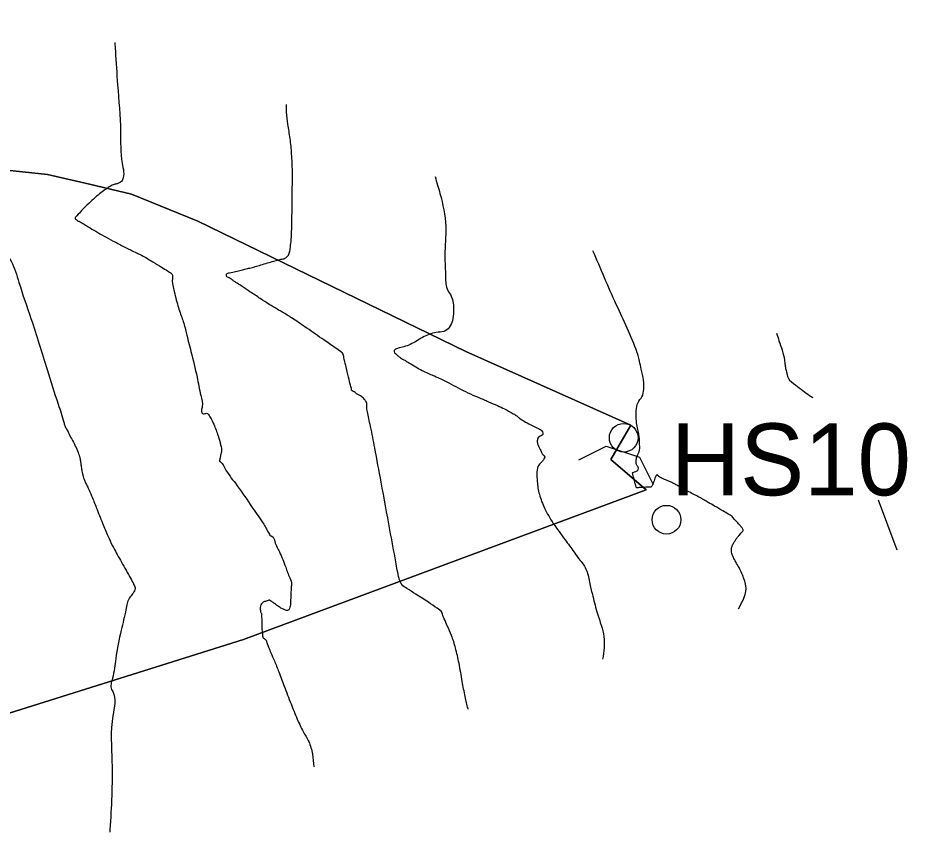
# Model space of a CAD drawing. Extents: x -478495 to -472450, y -1118050 to -1113745.
# Drawn here: x -476892.7 to -476768.9, y -1116354.3 to -1116241 of the extents above; entities that cross this region are included whole.
import ezdxf

# ---------------------------------------------------------------- set-up
doc = ezdxf.new("R2010")
doc.units = 0
for name, color, linetype in [('cesty', 7, 'Continuous'), ('hospodářské sjezdy', 7, 'Continuous'), ('ObPÚ', 7, 'Continuous'), ('Vrstevnice_hlavni', 7, 'Continuous'), ('Vrstevnice_vedlejsi', 7, 'Continuous')]:
    doc.layers.add(name, color=color, linetype=linetype)

msp = doc.modelspace()

# ---------------------------------------------------------------- linework, layer by layer
at = {"layer": 'cesty'}
for centre in [(-476808.34, -1116299.4), (-476802.39, -1116310.81)]:
    msp.add_circle(centre, 2, dxfattribs=at)
at = {"layer": 'hospodářské sjezdy'}
for p, q in [((-476814.6, -1116302.47), (-476810.79, -1116300.56)), ((-476810.79, -1116300.56), (-476806.15, -1116302.09)), ((-476806.15, -1116302.09), (-476804.23, -1116305.9))]:
    msp.add_line(p, q, dxfattribs=at)
at = {"layer": 'ObPÚ'}
for p, q in [((-476908.04, -1116260.74), (-476888.56, -1116262.76)), ((-476888.56, -1116262.76), (-476908.04, -1116260.74)), ((-476888.56, -1116262.76), (-476882.72, -1116264.13)), ((-476882.72, -1116264.13), (-476888.56, -1116262.76)), ((-476882.72, -1116264.13), (-476876.87, -1116265.5)), ((-476876.87, -1116265.5), (-476882.72, -1116264.13)), ((-476876.87, -1116265.5), (-476867.65, -1116269.24)), ((-476867.65, -1116269.24), (-476876.87, -1116265.5)), ((-476867.65, -1116269.24), (-476830.31, -1116287.39)), ((-476830.31, -1116287.39), (-476867.65, -1116269.24)), ((-476830.31, -1116287.39), (-476807.36, -1116297.66)), ((-476807.36, -1116297.66), (-476830.31, -1116287.39)), ((-476807.36, -1116297.66), (-476810.13, -1116302.43)), ((-476810.13, -1116302.43), (-476807.36, -1116297.66)), ((-476810.13, -1116302.43), (-476805.23, -1116306.64)), ((-476805.23, -1116306.64), (-476810.13, -1116302.43)), ((-476805.23, -1116306.64), (-476861.27, -1116327.48)), ((-476861.27, -1116327.48), (-476805.23, -1116306.64)), ((-476861.27, -1116327.48), (-476910.57, -1116342.96)), ((-476910.57, -1116342.96), (-476861.27, -1116327.48))]:
    msp.add_line(p, q, dxfattribs=at)
at = {"layer": 'Vrstevnice_hlavni'}
for points in [[(-476879.21, -1116244.41), (-476879.13, -1116245.59), (-476878.82, -1116250.29), (-476878.41, -1116256.78), (-476878.18, -1116261.19), (-476878.14, -1116263.5), (-476878.28, -1116263.72), (-476878.52, -1116263.9), (-476878.86, -1116264.05), (-476879.3, -1116264.16), (-476879.82, -1116264.41), (-476880.43, -1116264.79), (-476881.13, -1116265.3), (-476881.93, -1116265.97), (-476882.84, -1116266.8), (-476883.86, -1116267.79), (-476884.49, -1116268.5), (-476884.74, -1116268.91), (-476884.61, -1116269.04), (-476884.46, -1116269.14), (-476884.3, -1116269.24), (-476884.13, -1116269.31), (-476883.67, -1116269.57), (-476882.91, -1116270.03), (-476881.86, -1116270.67), (-476880.71, -1116271.33), (-476879.45, -1116272.02), (-476878.08, -1116272.72), (-476876.99, -1116273.27), (-476876.18, -1116273.67), (-476875.66, -1116273.91), (-476874.9, -1116274.33), (-476873.91, -1116274.91), (-476872.7, -1116275.65), (-476871.85, -1116276.18), (-476871.36, -1116276.5), (-476871.25, -1116276.6), (-476871.19, -1116276.79), (-476871.17, -1116277.1), (-476871.2, -1116277.5), (-476871.12, -1116278.15), (-476870.93, -1116279.06), (-476870.64, -1116280.23), (-476870.34, -1116281.28), (-476870.04, -1116282.22), (-476869.74, -1116283.03), (-476869.26, -1116284.77), (-476868.6, -1116287.41), (-476867.76, -1116290.96), (-476867.23, -1116293.51), (-476867.03, -1116295.06), (-476867.14, -1116295.59), (-476867.08, -1116295.93), (-476866.85, -1116296.07), (-476866.43, -1116296), (-476865.96, -1116296.49), (-476865.42, -1116297.53)], [(-476865.42, -1116297.53), (-476864.82, -1116299.12), (-476864.47, -1116300.4), (-476864.36, -1116301.35), (-476864.51, -1116301.99), (-476864.59, -1116302.43), (-476864.61, -1116302.67), (-476864.55, -1116302.72), (-476863.83, -1116303.73), (-476862.42, -1116305.73), (-476860.34, -1116308.69), (-476858.89, -1116310.81), (-476858.07, -1116312.09), (-476857.87, -1116312.53), (-476857.68, -1116312.84), (-476857.5, -1116313.03), (-476857.33, -1116313.1), (-476856.92, -1116313.85), (-476856.28, -1116315.28), (-476855.41, -1116317.4), (-476854.84, -1116318.91), (-476854.58, -1116319.81), (-476854.63, -1116320.11), (-476854.67, -1116320.66), (-476854.71, -1116321.45), (-476854.74, -1116322.5), (-476854.88, -1116323.16), (-476855.14, -1116323.45), (-476855.51, -1116323.36), (-476855.94, -1116323.16), (-476856.43, -1116322.87), (-476856.97, -1116322.48), (-476857.36, -1116322.21), (-476857.6, -1116322.05), (-476857.68, -1116322), (-476857.86, -1116322.03), (-476858.14, -1116322.13), (-476858.53, -1116322.3), (-476858.79, -1116322.53), (-476858.93, -1116322.83), (-476858.95, -1116323.18), (-476858.94, -1116323.45), (-476858.9, -1116323.64), (-476858.83, -1116323.76), (-476858.77, -1116324.2), (-476858.73, -1116324.97), (-476858.72, -1116326.07), (-476858.64, -1116326.84), (-476858.51, -1116327.29), (-476858.31, -1116327.42), (-476858.16, -1116327.58), (-476858.06, -1116327.78), (-476858, -1116328.02), (-476857.8, -1116328.54), (-476857.47, -1116329.35), (-476856.99, -1116330.44), (-476856.37, -1116331.98), (-476855.6, -1116333.98), (-476854.67, -1116336.44), (-476853.8, -1116338.55), (-476852.97, -1116340.3), (-476852.2, -1116341.69), (-476851.7, -1116343.42), (-476851.51, -1116345.19)]]:
    msp.add_spline(points, degree=3, dxfattribs=at)
at = {"layer": 'Vrstevnice_vedlejsi'}
msp.add_line((-476772.89, -1116308.03), (-476770.29, -1116314.98), dxfattribs=at)
for points in [[(-476904.91, -1116240.96), (-476904.89, -1116241.08), (-476904.25, -1116243.09), (-476904.01, -1116246.21), (-476904.18, -1116250.45), (-476904.76, -1116255.81), (-476905.12, -1116259.68), (-476905.25, -1116262.06), (-476905.17, -1116262.95), (-476905.07, -1116263.68), (-476904.96, -1116264.25), (-476904.83, -1116264.67), (-476904.55, -1116265.56), (-476904.1, -1116266.95), (-476903.5, -1116268.81), (-476902.73, -1116270.17), (-476901.79, -1116271.02), (-476900.68, -1116271.38), (-476899.6, -1116271.65), (-476898.56, -1116271.85), (-476897.54, -1116271.97), (-476896.76, -1116272.13), (-476896.22, -1116272.31), (-476895.92, -1116272.53), (-476895.67, -1116272.69), (-476895.49, -1116272.8), (-476895.36, -1116272.85), (-476895.21, -1116272.91), (-476895.04, -1116272.98), (-476894.85, -1116273.06), (-476894.56, -1116273.39), (-476894.16, -1116273.99), (-476893.65, -1116274.84), (-476892.56, -1116277.78), (-476890.88, -1116282.81), (-476888.63, -1116289.92), (-476887.1, -1116294.73), (-476886.3, -1116297.25), (-476886.24, -1116297.47), (-476886.15, -1116297.7), (-476886.05, -1116297.95), (-476885.92, -1116298.2), (-476885.66, -1116298.72), (-476885.25, -1116299.5), (-476884.71, -1116300.55), (-476884.31, -1116301.44), (-476884.07, -1116302.19), (-476883.97, -1116302.78), (-476883.9, -1116303.26), (-476883.85, -1116303.64), (-476883.81, -1116303.91), (-476883.75, -1116304.23), (-476883.66, -1116304.58), (-476883.55, -1116304.98), (-476883.38, -1116305.42), (-476883.17, -1116305.89), (-476882.91, -1116306.41), (-476882.44, -1116307.48), (-476881.78, -1116309.11), (-476880.92, -1116311.29), (-476880.17, -1116313.07), (-476879.53, -1116314.45)], [(-476862.17, -1116277.89), (-476862.52, -1116277.66), (-476862.88, -1116277.42), (-476863.26, -1116277.16), (-476863.66, -1116276.89), (-476863.64, -1116276.65), (-476863.22, -1116276.44), (-476862.38, -1116276.25), (-476861.61, -1116276.07), (-476860.9, -1116275.9), (-476860.24, -1116275.74), (-476859.49, -1116275.53), (-476858.65, -1116275.28), (-476857.72, -1116275), (-476856.9, -1116274.77), (-476856.21, -1116274.59), (-476855.64, -1116274.48), (-476855.21, -1116274.19), (-476854.92, -1116273.73), (-476854.78, -1116273.1), (-476854.67, -1116272.11), (-476854.59, -1116270.76), (-476854.55, -1116269.06), (-476854.51, -1116267.08), (-476854.49, -1116264.82), (-476854.48, -1116262.29), (-476854.58, -1116259.93), (-476854.79, -1116257.76), (-476855.11, -1116255.77), (-476855.29, -1116254.08), (-476855.32, -1116253)], [(-476834.61, -1116263.06), (-476833.93, -1116265.41), (-476833.13, -1116269.99), (-476833.24, -1116274.04), (-476833.15, -1116277), (-476832.85, -1116278.89), (-476832.36, -1116279.69), (-476832.09, -1116280.66), (-476832.03, -1116281.81), (-476832.19, -1116283.12), (-476832.64, -1116284.05), (-476833.4, -1116284.59), (-476834.45, -1116284.74), (-476835.43, -1116285.01), (-476836.35, -1116285.43), (-476837.2, -1116285.97), (-476838.06, -1116286.4), (-476838.95, -1116286.74), (-476839.85, -1116286.97), (-476840.29, -1116287.25), (-476840.26, -1116287.59)], [(-476804.28, -1116305.84), (-476804.37, -1116306.05), (-476804.48, -1116306.2), (-476804.58, -1116306.27), (-476804.69, -1116306.27), (-476804.92, -1116306.27), (-476805.26, -1116306.29), (-476805.72, -1116306.32), (-476806.08, -1116306.34), (-476806.32, -1116306.35), (-476806.45, -1116306.36), (-476806.55, -1116306.32), (-476806.62, -1116306.22), (-476806.66, -1116306.06), (-476806.73, -1116305.79), (-476806.83, -1116305.39), (-476806.97, -1116304.88), (-476807.06, -1116304.53), (-476807.12, -1116304.34), (-476807.15, -1116304.31), (-476807.05, -1116304.25), (-476806.82, -1116304.15), (-476806.47, -1116304.02), (-476806.31, -1116303.8), (-476806.34, -1116303.5), (-476806.56, -1116303.1), (-476806.62, -1116302.62), (-476806.5, -1116302.04), (-476806.21, -1116301.38), (-476806.12, -1116300.33), (-476806.24, -1116298.91), (-476806.57, -1116297.1), (-476806.6, -1116295.63), (-476806.35, -1116294.49), (-476805.8, -1116293.7), (-476805.54, -1116292.66), (-476805.57, -1116291.38), (-476805.89, -1116289.86), (-476806.14, -1116288.72), (-476806.33, -1116287.95), (-476806.46, -1116287.56), (-476809.37, -1116280.84), (-476812.62, -1116273.39)], [(-476830, -1116337.19), (-476830.02, -1116337.11), (-476830.41, -1116335.43), (-476830.83, -1116333.32), (-476831.27, -1116330.79), (-476831.77, -1116328.65), (-476832.32, -1116326.92), (-476832.91, -1116325.58), (-476833.33, -1116324.6), (-476833.59, -1116323.97), (-476833.67, -1116323.69), (-476834.32, -1116323.13), (-476835.53, -1116322.3), (-476837.31, -1116321.18), (-476838.55, -1116320.36), (-476839.24, -1116319.83), (-476839.38, -1116319.59), (-476839.49, -1116319.37), (-476839.58, -1116319.17), (-476839.63, -1116318.99), (-476840.08, -1116316.67), (-476840.9, -1116312.2), (-476842.11, -1116305.59), (-476843.01, -1116300.8), (-476843.59, -1116297.83), (-476843.85, -1116296.7), (-476844.03, -1116295.78), (-476844.12, -1116295.08), (-476844.12, -1116294.61), (-476844.36, -1116294.15), (-476844.83, -1116293.7), (-476845.53, -1116293.27), (-476846, -1116292.95), (-476846.24, -1116292.76), (-476846.24, -1116292.69), (-476846.38, -1116292.1), (-476846.65, -1116290.99), (-476847.04, -1116289.35), (-476847.31, -1116288.24), (-476847.45, -1116287.68), (-476847.47, -1116287.65), (-476847.49, -1116287.62), (-476847.53, -1116287.59), (-476847.58, -1116287.54), (-476847.63, -1116287.51), (-476847.67, -1116287.48), (-476847.7, -1116287.46), (-476848.51, -1116286.9), (-476850.1, -1116285.79), (-476852.46, -1116284.15), (-476854.34, -1116282.88), (-476855.72, -1116282), (-476856.62, -1116281.5), (-476857.7, -1116280.84), (-476858.95, -1116280.03), (-476860.39, -1116279.07), (-476861.46, -1116278.35), (-476862.17, -1116277.89)], [(-476787.05, -1116284.84), (-476786.72, -1116285.9), (-476785.95, -1116288.59), (-476785.87, -1116289.27), (-476785.76, -1116289.91), (-476785.61, -1116290.52), (-476785.43, -1116291.08), (-476784.38, -1116292.08), (-476782.45, -1116293.52), (-476781.99, -1116293.81)], [(-476840.26, -1116287.59), (-476839.78, -1116287.98), (-476839.41, -1116288.27), (-476839.17, -1116288.44), (-476839.04, -1116288.5), (-476838.65, -1116288.72), (-476837.99, -1116289.11), (-476837.07, -1116289.67), (-476836.21, -1116290.14), (-476835.43, -1116290.51), (-476834.71, -1116290.8), (-476833.79, -1116291.22), (-476832.69, -1116291.77), (-476831.39, -1116292.46), (-476830.04, -1116293.13), (-476828.62, -1116293.77), (-476827.15, -1116294.39), (-476825.92, -1116294.93), (-476824.93, -1116295.39), (-476824.18, -1116295.78), (-476823.57, -1116296.14), (-476823.11, -1116296.45), (-476822.8, -1116296.73), (-476822.21, -1116297.1), (-476821.35, -1116297.57), (-476820.22, -1116298.12), (-476819.64, -1116298.59), (-476819.61, -1116298.96), (-476820.12, -1116299.25), (-476820.36, -1116299.67), (-476820.33, -1116300.23), (-476820.03, -1116300.92), (-476819.77, -1116301.44), (-476819.54, -1116301.79), (-476819.35, -1116301.97), (-476819.4, -1116302.26), (-476819.67, -1116302.67), (-476820.18, -1116303.21), (-476820.42, -1116304.15), (-476820.39, -1116305.5), (-476820.09, -1116307.27), (-476819.35, -1116309.21), (-476818.15, -1116311.31), (-476816.51, -1116313.59), (-476815.26, -1116315.31), (-476814.39, -1116316.49), (-476813.9, -1116317.11), (-476813.52, -1116317.86), (-476813.24, -1116318.74), (-476813.06, -1116319.74), (-476812.64, -1116321.46), (-476811.99, -1116323.91), (-476811.09, -1116327.07), (-476811.28, -1116330.23)], [(-476792.35, -1116323.19), (-476791.33, -1116319.99), (-476791.57, -1116319.12), (-476791.89, -1116318.28), (-476792.28, -1116317.47), (-476792.74, -1116316.68), (-476793.07, -1116316.02), (-476793.27, -1116315.5), (-476793.34, -1116315.11), (-476793.31, -1116314.72), (-476793.18, -1116314.33), (-476792.95, -1116313.93), (-476792.72, -1116313.56), (-476792.48, -1116313.23), (-476792.23, -1116312.94), (-476792.02, -1116312.69), (-476791.85, -1116312.49), (-476791.72, -1116312.33), (-476791.79, -1116312.05), (-476792.09, -1116311.65), (-476792.59, -1116311.12), (-476792.95, -1116310.74), (-476793.17, -1116310.48), (-476793.26, -1116310.36), (-476793.71, -1116310.06), (-476794.52, -1116309.58), (-476795.68, -1116308.91), (-476796.57, -1116308.4), (-476797.18, -1116308.05), (-476797.52, -1116307.85), (-476798.01, -1116307.58), (-476798.65, -1116307.24), (-476799.45, -1116306.84), (-476800.14, -1116306.48), (-476800.71, -1116306.16), (-476801.18, -1116305.88), (-476801.63, -1116305.64), (-476802.07, -1116305.44), (-476802.51, -1116305.27), (-476802.85, -1116305.12), (-476803.12, -1116304.99), (-476803.29, -1116304.88), (-476803.45, -1116304.77), (-476803.58, -1116304.66), (-476803.69, -1116304.56), (-476803.81, -1116304.63), (-476803.93, -1116304.85), (-476804.05, -1116305.23), (-476804.17, -1116305.56), (-476804.28, -1116305.84)], [(-476879.53, -1116314.45), (-476879, -1116315.41), (-476878.43, -1116316.45), (-476877.8, -1116317.55), (-476877.14, -1116318.73), (-476876.67, -1116319.6), (-476876.42, -1116320.15), (-476876.37, -1116320.38), (-476876.48, -1116320.71), (-476876.73, -1116321.14), (-476877.15, -1116321.66), (-476877.67, -1116323.33), (-476878.32, -1116326.16), (-476879.08, -1116330.13), (-476879.53, -1116332.88), (-476879.67, -1116334.42), (-476879.5, -1116334.72), (-476879.48, -1116338.08), (-476879.6, -1116344.48), (-476879.88, -1116353.94), (-476879.9, -1116354.29)]]:
    msp.add_spline(points, degree=3, dxfattribs=at)

# ---------------------------------------------------------------- texts
at = {"layer": 'hospodářské sjezdy'}
msp.add_text('HS10', height=10, rotation=360, dxfattribs=at).set_placement((-476801.79, -1116307.41))

doc.saveas('drawing.dxf')
